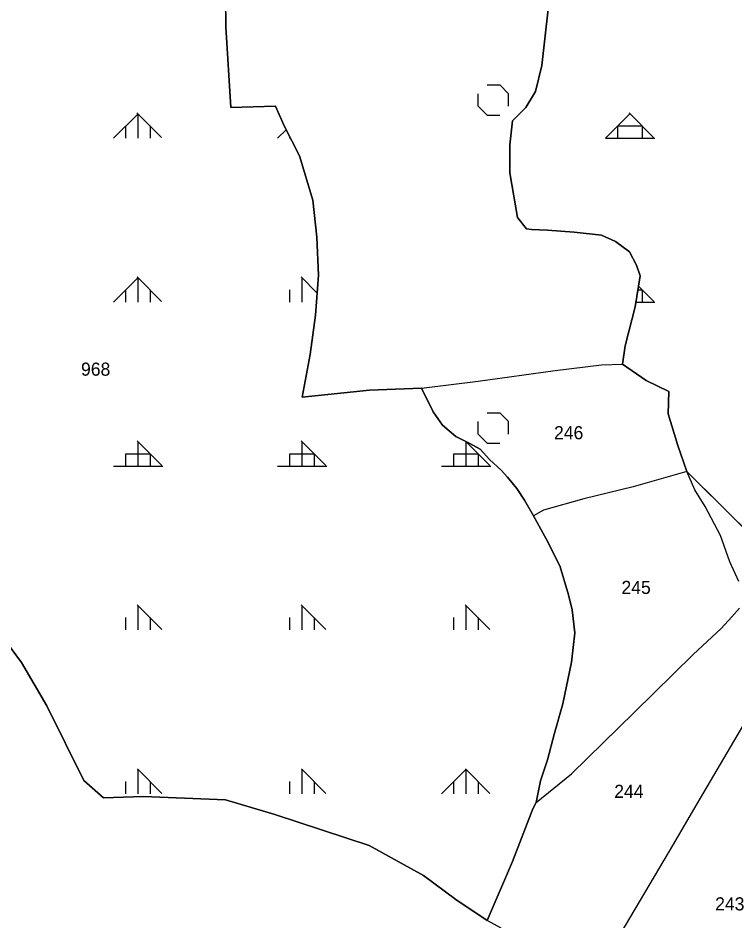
# Model space of a CAD drawing. Extents: x 410727 to 412947, y 4463506 to 4466382.
# Drawn here: x 411976.1 to 412194.6, y 4465547.1 to 4465822.5 of the extents above; entities that cross this region are included whole.
import ezdxf

# ---------------------------------------------------------------- set-up
doc = ezdxf.new("R2010")
doc.units = 0
for name, color, linetype in [('ADAKENARI', 7, 'Continuous'), ('KDS_PARSEL_NO', 7, 'Continuous'), ('KDS_PL', 7, 'Continuous'), ('PL_AYA_ORMAN', 7, 'Continuous'), ('PL_KA_TARIM_DIGER', 7, 'Continuous'), ('TR_ORMAN', 7, 'Continuous'), ('TR_TARIMALANI', 7, 'Continuous')]:
    doc.layers.add(name, color=color, linetype=linetype)

msp = doc.modelspace()

# ---------------------------------------------------------------- linework, layer by layer
at = {"layer": 'ADAKENARI'}
for p, q in [((412039.23, 4465838.68), (412039.44, 4465819.85)), ((412135.76, 4465808.08), (412137.68, 4465825.2)), ((412039.44, 4465819.85), (412040.94, 4465795.25)), ((412039.44, 4465819.85), (412040.94, 4465795.25)), ((412133.84, 4465800.17), (412135.76, 4465808.08)), ((412130.85, 4465795.25), (412133.84, 4465800.17)), ((412130.85, 4465795.25), (412133.84, 4465800.17)), ((412040.94, 4465795.25), (412054.6, 4465795.67)), ((412054.6, 4465795.67), (412057.17, 4465789.68)), ((412126.79, 4465791.18), (412130.85, 4465795.25)), ((412057.17, 4465789.68), (412061.86, 4465780.48)), ((412125.94, 4465783.9), (412126.79, 4465791.18)), ((412125.94, 4465775.34), (412125.94, 4465783.9)), ((412061.86, 4465780.48), (412065.92, 4465767)), ((412128.29, 4465761.65), (412125.94, 4465775.34)), ((412065.92, 4465767), (412067.2, 4465755.66)), ((412131.06, 4465758.23), (412128.29, 4465761.65)), ((412132.56, 4465758.01), (412131.06, 4465758.23)), ((412137.47, 4465757.8), (412132.56, 4465758.01)), ((412145.58, 4465757.16), (412137.47, 4465757.8)), ((412153.91, 4465756.3), (412145.58, 4465757.16)), ((412158.18, 4465754.38), (412153.91, 4465756.3)), ((412067.2, 4465755.66), (412067.63, 4465744.1)), ((412162.46, 4465751.17), (412158.18, 4465754.38)), ((412164.59, 4465747.1), (412162.46, 4465751.17)), ((412165.66, 4465743.89), (412164.59, 4465747.1)), ((412067.63, 4465744.1), (412066.78, 4465731.91)), ((412164.16, 4465734.47), (412165.66, 4465743.89)), ((412161.17, 4465722.49), (412164.16, 4465734.47)), ((412066.78, 4465731.91), (412065.07, 4465719.92)), ((412160.32, 4465716.93), (412161.17, 4465722.49)), ((412065.07, 4465719.92), (412062.72, 4465706.87)), ((412167.58, 4465712.01), (412160.32, 4465716.93)), ((412174.42, 4465708.58), (412167.58, 4465712.01)), ((412062.72, 4465706.87), (412083.22, 4465709.01)), ((412083.22, 4465709.01), (412099.03, 4465709.65)), ((412099.03, 4465709.65), (412102.66, 4465702.38)), ((412174.2, 4465701.74), (412174.42, 4465708.58)), ((412102.66, 4465702.38), (412105.43, 4465698.31)), ((412177.19, 4465692.11), (412174.2, 4465701.74)), ((412105.43, 4465698.31), (412109.49, 4465694.89)), ((412109.49, 4465694.89), (412113.76, 4465692.75)), ((412113.76, 4465692.75), (412116.97, 4465691.04)), ((412116.97, 4465691.04), (412119.74, 4465687.83)), ((412179.97, 4465684.19), (412177.19, 4465692.11)), ((412119.74, 4465687.83), (412123.37, 4465684.62)), ((412123.37, 4465684.62), (412125.3, 4465682.48)), ((412225.68, 4465638.78), (412179.97, 4465684.19)), ((412125.3, 4465682.48), (412128.07, 4465679.05)), ((412128.07, 4465679.05), (412130.42, 4465675.42)), ((412130.42, 4465675.42), (412133.2, 4465670.71)), ((412133.2, 4465670.71), (412137.68, 4465662.58)), ((412137.68, 4465662.58), (412141.32, 4465655.09)), ((412141.32, 4465655.09), (412143.88, 4465646.53)), ((412143.88, 4465646.53), (412144.94, 4465642.04)), ((412144.94, 4465642.04), (412145.8, 4465634.97)), ((411977.17, 4465625.96), (411967.3, 4465639.14)), ((412145.8, 4465634.97), (412144.73, 4465625.99)), ((411984.89, 4465612.68), (411977.17, 4465625.96)), ((412144.73, 4465625.99), (412142.17, 4465613.36)), ((411996.1, 4465589.93), (411984.89, 4465612.68)), ((412142.17, 4465613.36), (412139.61, 4465604.38)), ((412139.61, 4465604.38), (412137.47, 4465596.24)), ((412137.47, 4465596.24), (412135.33, 4465589.83)), ((412002.17, 4465584.68), (411996.1, 4465589.93)), ((412135.33, 4465589.83), (412134.05, 4465583.19)), ((412014.31, 4465585.09), (412002.17, 4465584.68)), ((412039.31, 4465584.06), (412014.31, 4465585.09)), ((412054.33, 4465579.53), (412039.31, 4465584.06)), ((412134.05, 4465583.19), (412132.99, 4465581.26)), ((412083.14, 4465570.06), (412054.33, 4465579.53)), ((412132.99, 4465581.26), (412126.79, 4465565.21)), ((412099.7, 4465560.9), (412083.14, 4465570.06)), ((412126.79, 4465565.21), (412119.1, 4465547.24)), ((412109.47, 4465553.59), (412099.7, 4465560.9)), ((412119.1, 4465547.24), (412109.47, 4465553.59))]:
    msp.add_line(p, q, dxfattribs=at)
at = {"layer": 'KDS_PL'}
for p, q in [((412039.23, 4465838.68), (412039.44, 4465819.85)), ((412135.76, 4465808.08), (412137.68, 4465825.2)), ((412039.44, 4465819.85), (412040.94, 4465795.25)), ((412133.84, 4465800.17), (412135.76, 4465808.08)), ((412130.85, 4465795.25), (412133.84, 4465800.17)), ((412040.94, 4465795.25), (412054.6, 4465795.67)), ((412054.6, 4465795.67), (412057.17, 4465789.68)), ((412126.79, 4465791.18), (412130.85, 4465795.25)), ((412057.17, 4465789.68), (412061.86, 4465780.48)), ((412125.94, 4465783.9), (412126.79, 4465791.18)), ((412125.94, 4465775.34), (412125.94, 4465783.9)), ((412061.86, 4465780.48), (412065.92, 4465767)), ((412128.29, 4465761.65), (412125.94, 4465775.34)), ((412065.92, 4465767), (412067.2, 4465755.66)), ((412131.06, 4465758.23), (412128.29, 4465761.65)), ((412132.56, 4465758.01), (412131.06, 4465758.23)), ((412137.47, 4465757.8), (412132.56, 4465758.01)), ((412145.58, 4465757.16), (412137.47, 4465757.8)), ((412153.91, 4465756.3), (412145.58, 4465757.16)), ((412158.18, 4465754.38), (412153.91, 4465756.3)), ((412067.2, 4465755.66), (412067.63, 4465744.1)), ((412162.46, 4465751.17), (412158.18, 4465754.38)), ((412164.59, 4465747.1), (412162.46, 4465751.17)), ((412165.66, 4465743.89), (412164.59, 4465747.1)), ((412067.63, 4465744.1), (412066.78, 4465731.91)), ((412164.16, 4465734.47), (412165.66, 4465743.89)), ((412161.17, 4465722.49), (412164.16, 4465734.47)), ((412066.78, 4465731.91), (412065.07, 4465719.92)), ((412160.32, 4465716.93), (412161.17, 4465722.49)), ((412065.07, 4465719.92), (412062.72, 4465706.87)), ((412116.33, 4465711.79), (412139.82, 4465715)), ((412139.82, 4465715), (412153.91, 4465716.71)), ((412153.91, 4465716.71), (412160.32, 4465716.93)), ((412160.32, 4465716.93), (412167.58, 4465712.01)), ((412099.03, 4465709.65), (412116.33, 4465711.79)), ((412167.58, 4465712.01), (412174.42, 4465708.58)), ((412062.72, 4465706.87), (412083.22, 4465709.01)), ((412083.22, 4465709.01), (412099.03, 4465709.65)), ((412102.66, 4465702.38), (412099.03, 4465709.65)), ((412174.42, 4465708.58), (412174.2, 4465701.74)), ((412105.43, 4465698.31), (412102.66, 4465702.38)), ((412174.2, 4465701.74), (412177.19, 4465692.11)), ((412109.49, 4465694.89), (412105.43, 4465698.31)), ((412113.76, 4465692.75), (412109.49, 4465694.89)), ((412116.97, 4465691.04), (412113.76, 4465692.75)), ((412119.74, 4465687.83), (412116.97, 4465691.04)), ((412177.19, 4465692.11), (412179.97, 4465684.19)), ((412123.37, 4465684.62), (412119.74, 4465687.83)), ((412125.3, 4465682.48), (412123.37, 4465684.62)), ((412179.97, 4465684.19), (412163.53, 4465679.48)), ((412182.32, 4465678.63), (412179.97, 4465684.19)), ((412128.07, 4465679.05), (412125.3, 4465682.48)), ((412130.42, 4465675.42), (412128.07, 4465679.05)), ((412163.53, 4465679.48), (412148.58, 4465675.84)), ((412185.52, 4465673.49), (412182.32, 4465678.63)), ((412133.2, 4465670.71), (412130.42, 4465675.42)), ((412148.58, 4465675.84), (412136.19, 4465672.42)), ((412190.22, 4465664.72), (412185.52, 4465673.49)), ((412136.19, 4465672.42), (412133.2, 4465670.71)), ((412133.2, 4465670.71), (412137.68, 4465662.58)), ((412137.68, 4465662.58), (412141.32, 4465655.09)), ((412193, 4465656.59), (412190.22, 4465664.72)), ((412195.77, 4465650.59), (412193, 4465656.59)), ((412141.32, 4465655.09), (412143.88, 4465646.53)), ((412143.88, 4465646.53), (412144.94, 4465642.04)), ((412144.94, 4465642.04), (412145.8, 4465634.97)), ((412193.64, 4465639.9), (412195.99, 4465642.46)), ((411977.17, 4465625.96), (411967.3, 4465639.14)), ((412190.43, 4465636.26), (412193.64, 4465639.9)), ((412145.8, 4465634.97), (412144.73, 4465625.99)), ((412181.89, 4465628.34), (412190.43, 4465636.26)), ((412163.95, 4465610.79), (412181.89, 4465628.34)), ((411984.89, 4465612.68), (411977.17, 4465625.96)), ((412144.73, 4465625.99), (412142.17, 4465613.36)), ((411996.1, 4465589.93), (411984.89, 4465612.68)), ((412142.17, 4465613.36), (412139.61, 4465604.38)), ((412144.73, 4465591.96), (412163.95, 4465610.79)), ((412182.06, 4465581.09), (412197.29, 4465607.03)), ((412139.61, 4465604.38), (412137.47, 4465596.24)), ((412137.47, 4465596.24), (412135.33, 4465589.83)), ((412134.05, 4465583.19), (412144.73, 4465591.96)), ((412002.17, 4465584.68), (411996.1, 4465589.93)), ((412135.33, 4465589.83), (412134.05, 4465583.19)), ((412014.31, 4465585.09), (412002.17, 4465584.68)), ((412039.31, 4465584.06), (412014.31, 4465585.09)), ((412054.33, 4465579.53), (412039.31, 4465584.06)), ((412132.99, 4465581.26), (412134.05, 4465583.19)), ((412083.14, 4465570.06), (412054.33, 4465579.53)), ((412126.79, 4465565.21), (412132.99, 4465581.26)), ((412175.97, 4465570.6), (412182.06, 4465581.09)), ((412099.7, 4465560.9), (412083.14, 4465570.06)), ((412153.89, 4465533.41), (412175.97, 4465570.6)), ((412119.1, 4465547.24), (412126.79, 4465565.21)), ((412109.47, 4465553.59), (412099.7, 4465560.9)), ((412119.1, 4465547.24), (412109.47, 4465553.59)), ((412123.38, 4465544.89), (412119.1, 4465547.24))]:
    msp.add_line(p, q, dxfattribs=at)
at = {"layer": 'PL_AYA_ORMAN'}
for points in [[(411967.3, 4465639.14), (411977.17, 4465625.96), (411984.89, 4465612.68), (411996.1, 4465589.93), (412002.17, 4465584.68), (412014.31, 4465585.09), (412039.31, 4465584.06), (412054.33, 4465579.53), (412083.14, 4465570.06), (412099.7, 4465560.9), (412109.47, 4465553.59), (412119.1, 4465547.24), (412126.79, 4465565.21), (412132.99, 4465581.26), (412134.05, 4465583.19), (412135.33, 4465589.83), (412137.47, 4465596.24), (412139.61, 4465604.38), (412142.17, 4465613.36), (412144.73, 4465625.99), (412145.8, 4465634.97), (412144.94, 4465642.04), (412143.88, 4465646.53), (412141.32, 4465655.09), (412137.68, 4465662.58), (412133.2, 4465670.71), (412130.42, 4465675.42), (412128.07, 4465679.05), (412125.3, 4465682.48), (412123.37, 4465684.62), (412119.74, 4465687.83), (412116.97, 4465691.04), (412113.76, 4465692.75), (412109.49, 4465694.89), (412105.43, 4465698.31), (412102.66, 4465702.38), (412099.03, 4465709.65), (412083.22, 4465709.01), (412062.72, 4465706.87), (412065.07, 4465719.92), (412066.78, 4465731.91), (412067.63, 4465744.1), (412067.2, 4465755.66), (412065.92, 4465767), (412061.86, 4465780.48), (412057.17, 4465789.68), (412054.6, 4465795.67), (412040.94, 4465795.25), (412039.44, 4465819.85), (412039.23, 4465838.68)], [(412137.68, 4465825.2), (412135.76, 4465808.08), (412133.84, 4465800.17), (412130.85, 4465795.25), (412126.79, 4465791.18), (412125.94, 4465783.9), (412125.94, 4465775.34), (412128.29, 4465761.65), (412131.06, 4465758.23), (412132.56, 4465758.01), (412137.47, 4465757.8), (412145.58, 4465757.16), (412153.91, 4465756.3), (412158.18, 4465754.38), (412162.46, 4465751.17), (412164.59, 4465747.1), (412165.66, 4465743.89), (412164.16, 4465734.47), (412161.17, 4465722.49), (412160.32, 4465716.93), (412167.58, 4465712.01), (412174.42, 4465708.58), (412174.2, 4465701.74), (412177.19, 4465692.11), (412179.97, 4465684.19), (412225.68, 4465638.78)]]:
    msp.add_lwpolyline(points, dxfattribs=at)
at = {"layer": 'PL_KA_TARIM_DIGER'}
for points in [[(411967.3, 4465639.14), (411977.17, 4465625.96), (411984.89, 4465612.68), (411996.1, 4465589.93), (412002.17, 4465584.68), (412014.31, 4465585.09), (412039.31, 4465584.06), (412054.33, 4465579.53), (412083.14, 4465570.06), (412099.7, 4465560.9), (412109.47, 4465553.59), (412119.1, 4465547.24), (412126.79, 4465565.21), (412132.99, 4465581.26), (412134.05, 4465583.19), (412135.33, 4465589.83), (412137.47, 4465596.24), (412139.61, 4465604.38), (412142.17, 4465613.36), (412144.73, 4465625.99), (412145.8, 4465634.97), (412144.94, 4465642.04), (412143.88, 4465646.53), (412141.32, 4465655.09), (412137.68, 4465662.58), (412133.2, 4465670.71), (412130.42, 4465675.42), (412128.07, 4465679.05), (412125.3, 4465682.48), (412123.37, 4465684.62), (412119.74, 4465687.83), (412116.97, 4465691.04), (412113.76, 4465692.75), (412109.49, 4465694.89), (412105.43, 4465698.31), (412102.66, 4465702.38), (412099.03, 4465709.65), (412083.22, 4465709.01), (412062.72, 4465706.87), (412065.07, 4465719.92), (412066.78, 4465731.91), (412067.63, 4465744.1), (412067.2, 4465755.66), (412065.92, 4465767), (412061.86, 4465780.48), (412057.17, 4465789.68), (412054.6, 4465795.67), (412040.94, 4465795.25), (412039.44, 4465819.85), (412039.23, 4465838.68)], [(412137.68, 4465825.2), (412135.76, 4465808.08), (412133.84, 4465800.17), (412130.85, 4465795.25), (412126.79, 4465791.18), (412125.94, 4465783.9), (412125.94, 4465775.34), (412128.29, 4465761.65), (412131.06, 4465758.23), (412132.56, 4465758.01), (412137.47, 4465757.8), (412145.58, 4465757.16), (412153.91, 4465756.3), (412158.18, 4465754.38), (412162.46, 4465751.17), (412164.59, 4465747.1), (412165.66, 4465743.89), (412164.16, 4465734.47), (412161.17, 4465722.49), (412160.32, 4465716.93), (412167.58, 4465712.01), (412174.42, 4465708.58), (412174.2, 4465701.74), (412177.19, 4465692.11), (412179.97, 4465684.19), (412225.68, 4465638.78)]]:
    msp.add_lwpolyline(points, dxfattribs=at)
at = {"layer": 'TR_ORMAN'}
for p, q in [((412005.16, 4465785.85), (412012.66, 4465793.35)), ((412019.82, 4465786.08), (412012.32, 4465793.58)), ((412012.67, 4465785.86), (412012.67, 4465793.36)), ((412155.16, 4465785.87), (412162.66, 4465793.37)), ((412169.8, 4465786.08), (412162.3, 4465793.58)), ((412008.92, 4465785.86), (412008.92, 4465789.61)), ((412016.42, 4465785.86), (412016.42, 4465789.61)), ((412158.92, 4465785.86), (412158.92, 4465789.61)), ((412158.92, 4465789.61), (412166.42, 4465789.61)), ((412166.42, 4465785.86), (412166.42, 4465789.61)), ((412055.16, 4465785.86), (412057.78, 4465788.48)), ((412058.92, 4465785.86), (412058.92, 4465786.25)), ((412155.17, 4465785.86), (412170.17, 4465785.86)), ((412005.16, 4465735.86), (412012.66, 4465743.36)), ((412019.85, 4465736.06), (412012.35, 4465743.55)), ((412019.85, 4465736.06), (412012.35, 4465743.55)), ((412012.67, 4465735.86), (412012.67, 4465743.36)), ((412067.25, 4465738.65), (412062.35, 4465743.55)), ((412062.67, 4465735.86), (412062.67, 4465743.36)), ((412008.92, 4465735.86), (412008.92, 4465739.61)), ((412016.42, 4465735.86), (412016.42, 4465739.61)), ((412058.92, 4465735.86), (412058.92, 4465739.61)), ((412164.98, 4465739.61), (412166.42, 4465739.61)), ((412169.83, 4465736.06), (412165.16, 4465740.73)), ((412166.42, 4465735.86), (412166.42, 4465739.61)), ((412164.38, 4465735.86), (412170.17, 4465735.86)), ((412019.88, 4465686.03), (412012.39, 4465693.53)), ((412012.67, 4465685.86), (412012.67, 4465693.36)), ((412069.88, 4465686.03), (412062.38, 4465693.53)), ((412069.88, 4465686.03), (412062.38, 4465693.53)), ((412062.67, 4465685.86), (412062.67, 4465693.36)), ((412119.87, 4465686.03), (412112.54, 4465693.36)), ((412112.67, 4465685.86), (412112.67, 4465693.3)), ((412008.92, 4465685.86), (412008.92, 4465689.61)), ((412008.92, 4465689.61), (412016.42, 4465689.61)), ((412016.42, 4465685.86), (412016.42, 4465689.61)), ((412058.92, 4465685.86), (412058.92, 4465689.61)), ((412058.92, 4465689.61), (412066.42, 4465689.61)), ((412066.42, 4465685.86), (412066.42, 4465689.61)), ((412108.92, 4465685.86), (412108.92, 4465689.61)), ((412108.92, 4465689.61), (412116.42, 4465689.61)), ((412116.42, 4465685.86), (412116.42, 4465689.61)), ((412005.17, 4465685.86), (412020.17, 4465685.86)), ((412055.17, 4465685.86), (412070.17, 4465685.86)), ((412105.17, 4465685.86), (412120.17, 4465685.86)), ((412019.92, 4465636.01), (412012.42, 4465643.51)), ((412012.67, 4465635.86), (412012.67, 4465643.36)), ((412069.91, 4465636.01), (412062.41, 4465643.51)), ((412062.67, 4465635.86), (412062.67, 4465643.36)), ((412119.9, 4465636.01), (412112.4, 4465643.51)), ((412119.9, 4465636.01), (412112.4, 4465643.51)), ((412112.67, 4465635.86), (412112.67, 4465643.36)), ((412008.92, 4465635.86), (412008.92, 4465639.61)), ((412016.42, 4465635.86), (412016.42, 4465639.61)), ((412058.92, 4465635.86), (412058.92, 4465639.61)), ((412066.42, 4465635.86), (412066.42, 4465639.61)), ((412108.92, 4465635.86), (412108.92, 4465639.61)), ((412116.42, 4465635.86), (412116.42, 4465639.61)), ((412019.95, 4465585.98), (412012.45, 4465593.48)), ((412019.95, 4465585.98), (412012.45, 4465593.48)), ((412012.67, 4465585.86), (412012.67, 4465593.36)), ((412012.67, 4465585.86), (412012.67, 4465593.36)), ((412069.94, 4465585.98), (412062.44, 4465593.48)), ((412069.94, 4465585.98), (412062.44, 4465593.48)), ((412062.67, 4465585.86), (412062.67, 4465593.36)), ((412062.67, 4465585.86), (412062.67, 4465593.36)), ((412105.16, 4465585.89), (412112.66, 4465593.39)), ((412105.16, 4465585.89), (412112.66, 4465593.39)), ((412119.93, 4465585.98), (412112.43, 4465593.48)), ((412119.93, 4465585.98), (412112.43, 4465593.48)), ((412112.67, 4465585.86), (412112.67, 4465593.36)), ((412112.67, 4465585.86), (412112.67, 4465593.36)), ((412008.92, 4465585.86), (412008.92, 4465589.61)), ((412008.92, 4465585.86), (412008.92, 4465589.61)), ((412016.42, 4465585.86), (412016.42, 4465589.61)), ((412016.42, 4465585.86), (412016.42, 4465589.61)), ((412058.92, 4465585.86), (412058.92, 4465589.61)), ((412058.92, 4465585.86), (412058.92, 4465589.61)), ((412066.42, 4465585.86), (412066.42, 4465589.61)), ((412066.42, 4465585.86), (412066.42, 4465589.61)), ((412108.92, 4465585.86), (412108.92, 4465589.61)), ((412108.92, 4465585.86), (412108.92, 4465589.61)), ((412116.42, 4465585.86), (412116.42, 4465589.61)), ((412116.42, 4465585.86), (412116.42, 4465589.61))]:
    msp.add_line(p, q, dxfattribs=at)
at = {"layer": 'TR_TARIMALANI'}
for p, q in [((412119.08, 4465802.14), (412122.91, 4465802.14)), ((412125.62, 4465799.43), (412122.91, 4465802.14)), ((412125.62, 4465799.43), (412122.91, 4465802.14)), ((412116.37, 4465795.6), (412116.37, 4465799.43)), ((412116.37, 4465795.6), (412116.37, 4465799.43)), ((412125.62, 4465795.6), (412125.62, 4465799.43)), ((412119.08, 4465792.89), (412116.37, 4465795.6)), ((412119.08, 4465792.89), (412116.37, 4465795.6)), ((412119.08, 4465792.89), (412122.91, 4465792.89)), ((412119.08, 4465702.14), (412122.91, 4465702.14)), ((412125.62, 4465699.43), (412122.91, 4465702.14)), ((412116.37, 4465695.6), (412116.37, 4465699.43)), ((412116.37, 4465695.6), (412116.37, 4465699.43)), ((412125.62, 4465695.6), (412125.62, 4465699.43)), ((412119.08, 4465692.89), (412116.37, 4465695.6)), ((412119.08, 4465692.89), (412122.91, 4465692.89))]:
    msp.add_line(p, q, dxfattribs=at)

# ---------------------------------------------------------------- texts
at = {"layer": 'KDS_PARSEL_NO'}
for s, p in [('968', (411995.28, 4465713.42)), ('246', (412139.45, 4465694.03)), ('245', (412160.01, 4465646.84)), ('244', (412157.8, 4465584.62)), ('243', (412188.56, 4465550.3))]:
    msp.add_text(s, height=4, dxfattribs=at).set_placement(p)

doc.saveas('drawing.dxf')
